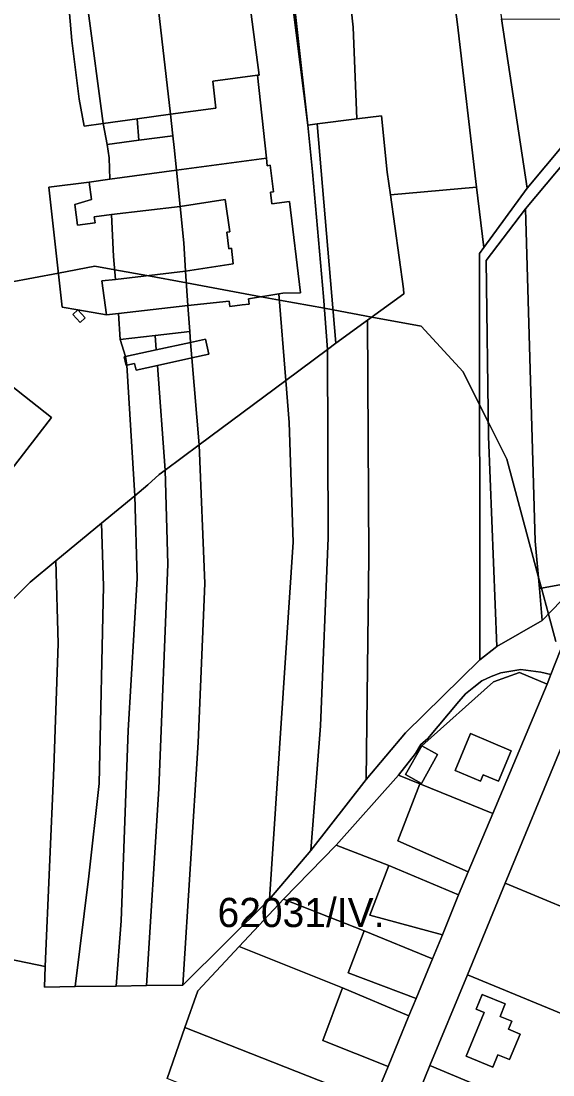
# Model space of a CAD drawing. Extents: x -502026 to -497664, y -1143484 to -1138019.
# Drawn here: x -498838.8 to -498692.8, y -1141174.4 to -1140885.3 of the extents above; entities that cross this region are included whole.
import ezdxf

# ---------------------------------------------------------------- set-up
doc = ezdxf.new("R2010")
doc.units = 0
for name, color, linetype in [('25', 7, 'Continuous'), ('37', 7, 'Continuous'), ('55', 7, 'Continuous'), ('62', 7, 'Continuous'), ('7', 7, 'Continuous')]:
    doc.layers.add(name, color=color, linetype=linetype)

msp = doc.modelspace()

# ---------------------------------------------------------------- linework, layer by layer
at = {"layer": '25'}
for points in [[(-498694.44, -1141067.19), (-498709.32, -1141102.7), (-498729.36, -1141094.57), (-498735.24, -1141092.18), (-498730.5, -1141086.22), (-498728.8, -1141084.07), (-498733.28, -1141091.97), (-498728.89, -1141094.43), (-498724.52, -1141086.52), (-498728.8, -1141084.07), (-498709.14, -1141066.52), (-498702, -1141064.02)], [(-498704.28, -1141085.44), (-498715.4, -1141080.72), (-498719.67, -1141090.85), (-498712.69, -1141093.79), (-498711.97, -1141092.05), (-498707.78, -1141093.82)], [(-498729.36, -1141094.57), (-498735.36, -1141110.17), (-498716.05, -1141118.64), (-498718.71, -1141124.96), (-498737.89, -1141116.91), (-498752.31, -1141111.36), (-498735.24, -1141092.18)], [(-498737.89, -1141116.91), (-498743.03, -1141130.57), (-498723.14, -1141135.96), (-498725.83, -1141142.54), (-498744.65, -1141134.88), (-498766.76, -1141126.14), (-498752.31, -1141111.36)], [(-498744.65, -1141134.88), (-498748.98, -1141146.4), (-498730.4, -1141153.42), (-498732.41, -1141158.21), (-498750.53, -1141150.51), (-498778.95, -1141139.15), (-498766.76, -1141126.14)], [(-498750.53, -1141150.51), (-498755.96, -1141164.93), (-498738.05, -1141172.05), (-498742.03, -1141181.8), (-498793.83, -1141161.35), (-498790.27, -1141151.29), (-498778.95, -1141139.15)], [(-498742.03, -1141181.8), (-498747.93, -1141195.66), (-498798.66, -1141175.38), (-498793.83, -1141161.35)]]:
    msp.add_lwpolyline(points, close=True, dxfattribs=at)
at = {"layer": '37'}
for points in [[(-498760.09, -1140913.85), (-498771.9, -1140820.4), (-498784.1, -1140820.16), (-498785.51, -1140809.66), (-498771.69, -1140809.65)], [(-498706.9, -1140884.67), (-498699.91, -1140931.17), (-498711.8, -1140947.43), (-498713.76, -1140930.86), (-498719.03, -1140886.28), (-498719.7, -1140880.66), (-498707.64, -1140879.42)], [(-498711.8, -1140947.43), (-498713.02, -1140949.03), (-498712.89, -1141060.49), (-498733.24, -1141080.57), (-498744.05, -1141093.39), (-498743.32, -1141032.24), (-498743.72, -1140967.38), (-498733.77, -1140960.11), (-498733.85, -1140958.78), (-498737.44, -1140932.98), (-498713.76, -1140930.86)], [(-498696.54, -1141040.99), (-498695.75, -1141049.74), (-498708.26, -1141056.85), (-498710.48, -1140999.24), (-498711.18, -1140950.97), (-498700.32, -1140936.82), (-498697.71, -1141027.94)], [(-498744.05, -1141093.39), (-498759.22, -1141112.84), (-498756.64, -1141078.64), (-498754.54, -1141027.06), (-498754.67, -1140975.4), (-498752.36, -1140973.7), (-498743.72, -1140967.38), (-498743.32, -1141032.24)], [(-498759.22, -1141112.84), (-498770.57, -1141126.2), (-498764.14, -1141028.27), (-498765.2, -1140995.4), (-498766.12, -1140983.89), (-498754.67, -1140975.4), (-498754.54, -1141027.06), (-498756.64, -1141078.64)], [(-498770.57, -1141126.2), (-498794.37, -1141149.74), (-498790.18, -1141083.22), (-498788.34, -1141039.56), (-498789.86, -1141001.5), (-498766.12, -1140983.89), (-498765.2, -1140995.4), (-498764.14, -1141028.27)], [(-498794.37, -1141149.74), (-498804.35, -1141149.88), (-498800.98, -1141095.92), (-498798.54, -1141034.25), (-498799.24, -1141008.45), (-498789.86, -1141001.5), (-498788.34, -1141039.56), (-498790.18, -1141083.22)], [(-498804.35, -1141149.88), (-498812.71, -1141150), (-498811.31, -1141132.09), (-498809.41, -1141079.94), (-498806.88, -1141038.23), (-498807.59, -1141015.49), (-498804.03, -1141012.54), (-498800.89, -1141009.68), (-498799.24, -1141008.45), (-498798.54, -1141034.25), (-498800.98, -1141095.92)], [(-498812.71, -1141150), (-498823.97, -1141150.16), (-498820.16, -1141119.89), (-498817.36, -1141094.49), (-498816.19, -1141040.27), (-498816.73, -1141023.06), (-498807.59, -1141015.49), (-498806.88, -1141038.23), (-498809.41, -1141079.94), (-498811.31, -1141132.09)], [(-498823.97, -1141150.16), (-498832.35, -1141150.28), (-498832.17, -1141144.65), (-498829.75, -1141090.15), (-498828.64, -1141056.05), (-498829.21, -1141033.39), (-498816.73, -1141023.06), (-498816.19, -1141040.27), (-498817.36, -1141094.49), (-498820.16, -1141119.89)], [(-498832.17, -1141144.65), (-498847.21, -1141141.55), (-498843.36, -1141108.57), (-498842.1, -1141045.05), (-498836.29, -1141039.26), (-498829.21, -1141033.39), (-498828.64, -1141056.05), (-498829.75, -1141090.15)], [(-498693.39, -1141064.53), (-498694.44, -1141067.19), (-498702, -1141064.02), (-498709.14, -1141066.52), (-498728.8, -1141084.07), (-498730.5, -1141086.22), (-498729.12, -1141083.73), (-498727.15, -1141082.09), (-498718.63, -1141071.99), (-498716.78, -1141069.84), (-498714.56, -1141068.03), (-498712.32, -1141066.29), (-498709.74, -1141065.12), (-498707.11, -1141064.06), (-498701.64, -1141063.15), (-498696.15, -1141063.95)], [(-498678.2, -1141133.3), (-498671.5, -1141136.07), (-498673.53, -1141140.98), (-498681.88, -1141161.17), (-498688.57, -1141158.4), (-498716.3, -1141146.93), (-498705.92, -1141121.83)], [(-498681.88, -1141161.17), (-498683.47, -1141165), (-498692.26, -1141186.25), (-498698.91, -1141183.44), (-498726.58, -1141171.76), (-498716.3, -1141146.93), (-498688.57, -1141158.4)], [(-498701.8, -1141163.17), (-498705.03, -1141161.83), (-498704.14, -1141159.67), (-498707.33, -1141158.34), (-498705.91, -1141154.9), (-498712.22, -1141152.29), (-498713.91, -1141156.34), (-498711.71, -1141157.23), (-498716.68, -1141169.2), (-498709.35, -1141172.25), (-498707.92, -1141168.84), (-498704.7, -1141170.17)]]:
    msp.add_lwpolyline(points, close=True, dxfattribs=at)
for points in [[(-498847.21, -1141141.55), (-498832.17, -1141144.65), (-498832.35, -1141150.28), (-498823.97, -1141150.16), (-498812.71, -1141150), (-498804.35, -1141149.88), (-498794.37, -1141149.74), (-498770.57, -1141126.2), (-498759.22, -1141112.84), (-498744.05, -1141093.39), (-498733.24, -1141080.57), (-498712.89, -1141060.49), (-498708.26, -1141056.85), (-498695.75, -1141049.74), (-498685.32, -1141038.97)], [(-498683.14, -1141038.57), (-498693.39, -1141064.53), (-498696.15, -1141063.95), (-498701.64, -1141063.15), (-498707.11, -1141064.06), (-498709.74, -1141065.12), (-498712.32, -1141066.29), (-498714.56, -1141068.03), (-498716.78, -1141069.84), (-498718.63, -1141071.99), (-498727.15, -1141082.09), (-498729.12, -1141083.73), (-498730.5, -1141086.22), (-498735.24, -1141092.18), (-498752.31, -1141111.36), (-498766.76, -1141126.14), (-498778.95, -1141139.15), (-498790.27, -1141151.29), (-498793.83, -1141161.35), (-498798.66, -1141175.38)], [(-498730.39, -1141180.99), (-498726.58, -1141171.76), (-498698.91, -1141183.44)]]:
    msp.add_lwpolyline(points, dxfattribs=at)
at = {"layer": '55'}
for points in [[(-498760.09, -1140913.85), (-498758.76, -1140926.62), (-498755.81, -1140960.83), (-498754.67, -1140975.4), (-498766.12, -1140983.89), (-498768.02, -1140960.13), (-498766.93, -1140959.95), (-498762.07, -1140959.81), (-498765.08, -1140934.83), (-498769.95, -1140935.42), (-498770.34, -1140932.22), (-498769.54, -1140932.12), (-498770.42, -1140924.87), (-498771.21, -1140924.97), (-498771.38, -1140922.91), (-498773.9, -1140900.18), (-498773.42, -1140900.12), (-498776.55, -1140876.33), (-498784.1, -1140820.16), (-498771.9, -1140820.4)], [(-498773.9, -1140900.18), (-498786.15, -1140901.82), (-498785.32, -1140909.16), (-498797.79, -1140910.87), (-498801.33, -1140879.84), (-498776.55, -1140876.33), (-498773.42, -1140900.12)], [(-498797.79, -1140910.87), (-498806.92, -1140912.12), (-498816.21, -1140913.4), (-498820.38, -1140882.54), (-498810.92, -1140881.2), (-498801.33, -1140879.84)], [(-498816.21, -1140913.4), (-498821.47, -1140914.09), (-498822.84, -1140906.7), (-498824.86, -1140890.63), (-498825.47, -1140883.24), (-498820.38, -1140882.54)], [(-498771.38, -1140922.91), (-498796.1, -1140926.18), (-498796.72, -1140919.95), (-498797.11, -1140916.8), (-498797.79, -1140910.87), (-498785.32, -1140909.16), (-498786.15, -1140901.82), (-498773.9, -1140900.18)], [(-498797.11, -1140916.8), (-498806.43, -1140918.01), (-498806.92, -1140912.12), (-498797.79, -1140910.87)], [(-498737.44, -1140932.98), (-498733.85, -1140958.78), (-498733.77, -1140960.11), (-498743.72, -1140967.38), (-498752.36, -1140973.7), (-498757.48, -1140913.5), (-498746.66, -1140912.14), (-498739.87, -1140911.28), (-498738.31, -1140926.71)], [(-498806.43, -1140918.01), (-498815.17, -1140919.15), (-498816.21, -1140913.4), (-498806.92, -1140912.12)], [(-498752.36, -1140973.7), (-498754.67, -1140975.4), (-498755.81, -1140960.83), (-498758.76, -1140926.62), (-498760.09, -1140913.85), (-498757.48, -1140913.5)], [(-498683.81, -1140917.04), (-498700.32, -1140936.82), (-498711.18, -1140950.97), (-498710.48, -1140999.24), (-498708.26, -1141056.85), (-498712.89, -1141060.49), (-498713.02, -1140949.03), (-498711.8, -1140947.43), (-498699.91, -1140931.17), (-498684.03, -1140912.22)], [(-498796.1, -1140926.18), (-498814.38, -1140928.66), (-498814.6, -1140922.78), (-498815.17, -1140919.15), (-498806.43, -1140918.01), (-498797.11, -1140916.8), (-498796.72, -1140919.95)], [(-498768.02, -1140960.13), (-498776.38, -1140961.49), (-498776.2, -1140962.93), (-498778.09, -1140963.15), (-498781.53, -1140963.56), (-498781.7, -1140962.12), (-498792.97, -1140963.32), (-498793.61, -1140953.88), (-498780.6, -1140951.91), (-498780.99, -1140947.6), (-498781.77, -1140947.77), (-498782.32, -1140943.21), (-498781.52, -1140943.12), (-498782.8, -1140934.29), (-498795.12, -1140936.15), (-498796.1, -1140926.18), (-498771.38, -1140922.91), (-498771.21, -1140924.97), (-498770.42, -1140924.87), (-498769.54, -1140932.12), (-498770.34, -1140932.22), (-498769.95, -1140935.42), (-498765.08, -1140934.83), (-498762.07, -1140959.81), (-498766.93, -1140959.95)], [(-498795.12, -1140936.15), (-498813.92, -1140938.35), (-498818.7, -1140938.97), (-498818.47, -1140940.65), (-498823.3, -1140941.27), (-498824.06, -1140935.66), (-498819.46, -1140934.28), (-498820.06, -1140929.52), (-498814.38, -1140928.66), (-498796.1, -1140926.18)], [(-498813.92, -1140938.35), (-498813.37, -1140949.92), (-498812.83, -1140956.15), (-498816.6, -1140956.55), (-498815.37, -1140965.91), (-498823.23, -1140964.53), (-498827.51, -1140963.78), (-498831.15, -1140930.87), (-498820.06, -1140929.52), (-498819.46, -1140934.28), (-498824.06, -1140935.66), (-498823.3, -1140941.27), (-498818.47, -1140940.65), (-498818.7, -1140938.97)], [(-498793.61, -1140953.88), (-498794.13, -1140946.14), (-498795.12, -1140936.15), (-498782.8, -1140934.29), (-498781.52, -1140943.12), (-498782.32, -1140943.21), (-498781.77, -1140947.77), (-498780.99, -1140947.6), (-498780.6, -1140951.91)], [(-498793.61, -1140953.88), (-498812.83, -1140956.15), (-498813.37, -1140949.92), (-498813.92, -1140938.35), (-498795.12, -1140936.15), (-498794.13, -1140946.14)], [(-498792.97, -1140963.32), (-498812.07, -1140965.56), (-498815.37, -1140965.91), (-498816.6, -1140956.55), (-498812.83, -1140956.15), (-498793.61, -1140953.88)], [(-498766.12, -1140983.89), (-498789.86, -1141001.5), (-498791.88, -1140977.67), (-498787.28, -1140976.65), (-498788.21, -1140972.59), (-498792.24, -1140973.46), (-498792.49, -1140970.5), (-498792.97, -1140963.32), (-498781.7, -1140962.12), (-498781.53, -1140963.56), (-498778.09, -1140963.15), (-498776.2, -1140962.93), (-498776.38, -1140961.49), (-498768.02, -1140960.13)], [(-498792.49, -1140970.5), (-498801.98, -1140971.58), (-498811.54, -1140972.67), (-498812.07, -1140965.56), (-498792.97, -1140963.32)], [(-498823.23, -1140964.53), (-498821.21, -1140966.7), (-498822.53, -1140967.95), (-498824.55, -1140965.75)], [(-498801.69, -1140975.49), (-498810.15, -1140977.31), (-498811.54, -1140972.67), (-498801.98, -1140971.58)], [(-498792.24, -1140973.46), (-498801.69, -1140975.49), (-498801.98, -1140971.58), (-498792.49, -1140970.5)], [(-498791.88, -1140977.67), (-498792.24, -1140973.46), (-498788.21, -1140972.59), (-498787.28, -1140976.65)], [(-498791.88, -1140977.67), (-498801.37, -1140979.76), (-498807.15, -1140981.03), (-498807.66, -1140979.24), (-498809.76, -1140979.7), (-498810.15, -1140977.31), (-498801.69, -1140975.49), (-498792.24, -1140973.46)], [(-498809.76, -1140979.7), (-498809.94, -1140979.74), (-498810.46, -1140977.38), (-498810.15, -1140977.31)], [(-498789.86, -1141001.5), (-498799.24, -1141008.45), (-498801.37, -1140979.76), (-498791.88, -1140977.67)], [(-498801.37, -1140979.76), (-498799.24, -1141008.45), (-498800.89, -1141009.68), (-498804.03, -1141012.54), (-498807.59, -1141015.49), (-498809.76, -1140979.7), (-498807.66, -1140979.24), (-498807.15, -1140981.03)], [(-498845.01, -1141012.81), (-498846.9, -1140991.66), (-498841.78, -1140985.12), (-498830.38, -1140994.02)], [(-498704.28, -1141085.44), (-498707.78, -1141093.82), (-498711.97, -1141092.05), (-498712.69, -1141093.79), (-498719.67, -1141090.85), (-498715.4, -1141080.72)], [(-498728.8, -1141084.07), (-498724.52, -1141086.52), (-498728.89, -1141094.43), (-498733.28, -1141091.97)], [(-498709.32, -1141102.7), (-498716.05, -1141118.64), (-498735.36, -1141110.17), (-498729.36, -1141094.57)], [(-498718.71, -1141124.96), (-498723.14, -1141135.96), (-498743.03, -1141130.57), (-498737.89, -1141116.91)], [(-498725.83, -1141142.54), (-498730.4, -1141153.42), (-498748.98, -1141146.4), (-498744.65, -1141134.88)], [(-498732.41, -1141158.21), (-498738.05, -1141172.05), (-498755.96, -1141164.93), (-498750.53, -1141150.51)], [(-498701.8, -1141163.17), (-498704.7, -1141170.17), (-498707.92, -1141168.84), (-498709.35, -1141172.25), (-498716.68, -1141169.2), (-498711.71, -1141157.23), (-498713.91, -1141156.34), (-498712.22, -1141152.29), (-498705.91, -1141154.9), (-498707.33, -1141158.34), (-498704.14, -1141159.67), (-498705.03, -1141161.83)]]:
    msp.add_lwpolyline(points, close=True, dxfattribs=at)
for points in [[(-498623.59, -1140877.34), (-498630.29, -1140897.47), (-498631.5, -1140901.1), (-498632.55, -1140907.09), (-498627.07, -1140908.5), (-498626.82, -1140908.92), (-498628.08, -1140914.21), (-498633.99, -1140912.47), (-498647.79, -1140960.45), (-498650.35, -1140969.02), (-498655.37, -1140985.43), (-498661.35, -1141005.13), (-498671.72, -1141039.24), (-498675.34, -1141047.9), (-498690.63, -1141084.87), (-498705.92, -1141121.83), (-498716.3, -1141146.93), (-498726.58, -1141171.76), (-498730.39, -1141180.99)], [(-498825.47, -1140883.24), (-498824.86, -1140890.63), (-498822.84, -1140906.7), (-498821.47, -1140914.09), (-498816.21, -1140913.4), (-498815.17, -1140919.15), (-498814.6, -1140922.78), (-498814.38, -1140928.66), (-498820.06, -1140929.52), (-498831.15, -1140930.87), (-498827.51, -1140963.78), (-498823.23, -1140964.53), (-498824.55, -1140965.75), (-498822.53, -1140967.95), (-498821.21, -1140966.7), (-498823.23, -1140964.53), (-498815.37, -1140965.91), (-498812.07, -1140965.56), (-498811.54, -1140972.67), (-498810.15, -1140977.31), (-498810.46, -1140977.38), (-498809.94, -1140979.74), (-498809.76, -1140979.7), (-498807.59, -1141015.49), (-498816.73, -1141023.06), (-498829.21, -1141033.39), (-498836.29, -1141039.26), (-498842.1, -1141045.05)], [(-498742.03, -1141181.8), (-498738.05, -1141172.05), (-498732.41, -1141158.21), (-498730.4, -1141153.42), (-498725.83, -1141142.54), (-498723.14, -1141135.96), (-498718.71, -1141124.96), (-498716.05, -1141118.64), (-498709.32, -1141102.7), (-498694.44, -1141067.19), (-498693.39, -1141064.53), (-498683.14, -1141038.57), (-498675.86, -1141020.14), (-498662.54, -1140971.73), (-498652.1, -1140935.02), (-498641.88, -1140898.03), (-498638.39, -1140886.47), (-498648.5, -1140886.18), (-498655.29, -1140885.89), (-498662.58, -1140885.36), (-498666.89, -1140885.25)], [(-498845.01, -1141012.81), (-498830.38, -1140994.02), (-498841.78, -1140985.12)]]:
    msp.add_lwpolyline(points, dxfattribs=at)
at = {"layer": '62'}
for points in [[(-498842.22, -1140957.05), (-498828.54, -1140954.43), (-498818.5, -1140952.5), (-498813.06, -1140953.5), (-498804.22, -1140955.13), (-498793.39, -1140957.13), (-498772.85, -1140960.91), (-498767.88, -1140961.83), (-498755.55, -1140964.1), (-498753.14, -1140964.55), (-498742.52, -1140966.51), (-498729, -1140969), (-498717.5, -1140981.5), (-498712.97, -1140990.56), (-498710.54, -1140995.43), (-498705.5, -1141005.5), (-498696.85, -1141037.54), (-498695.95, -1141040.88), (-498694.03, -1141047.97), (-498692, -1141055.5)], [(-498692, -1141055.5), (-498694.03, -1141047.97), (-498695.95, -1141040.88), (-498696.85, -1141037.54), (-498705.5, -1141005.5), (-498710.54, -1140995.43), (-498712.97, -1140990.56), (-498717.5, -1140981.5), (-498729, -1140969), (-498742.52, -1140966.51), (-498753.14, -1140964.55), (-498755.55, -1140964.1), (-498767.88, -1140961.83), (-498772.85, -1140960.91), (-498793.39, -1140957.13), (-498804.22, -1140955.13), (-498813.06, -1140953.5), (-498818.5, -1140952.5), (-498828.54, -1140954.43), (-498842.22, -1140957.05)]]:
    msp.add_lwpolyline(points, dxfattribs=at)
at = {"layer": '7'}
for points in [[(-498755.74, -1140812.42), (-498747.67, -1140886.95), (-498746.66, -1140912.14), (-498757.48, -1140913.5), (-498760.09, -1140913.85), (-498771.69, -1140809.65)], [(-498727.69, -1140814.18), (-498719.7, -1140880.66), (-498719.03, -1140886.28), (-498713.76, -1140930.86), (-498737.44, -1140932.98), (-498738.31, -1140926.71), (-498739.87, -1140911.28), (-498746.66, -1140912.14), (-498747.67, -1140886.95), (-498755.74, -1140812.42)], [(-498685.94, -1140884.74), (-498684.4, -1140904.28), (-498684.03, -1140912.22), (-498699.91, -1140931.17), (-498706.9, -1140884.67)], [(-498682.82, -1140929.67), (-498681.19, -1140966.4), (-498678.8, -1140994), (-498680.54, -1141019.61), (-498682.03, -1141032.16), (-498685.32, -1141038.97), (-498696.54, -1141040.99), (-498697.71, -1141027.94), (-498700.32, -1140936.82), (-498683.81, -1140917.04)], [(-498695.75, -1141049.74), (-498696.54, -1141040.99), (-498685.32, -1141038.97)], [(-498662.91, -1141096.33), (-498678.2, -1141133.3), (-498705.92, -1141121.83), (-498690.63, -1141084.87)]]:
    msp.add_lwpolyline(points, close=True, dxfattribs=at)

# ---------------------------------------------------------------- texts
at = {"layer": '62'}
msp.add_text('62031/IV.', height=8, dxfattribs=at).set_placement((-498784.86, -1141133.82))

doc.saveas('drawing.dxf')
